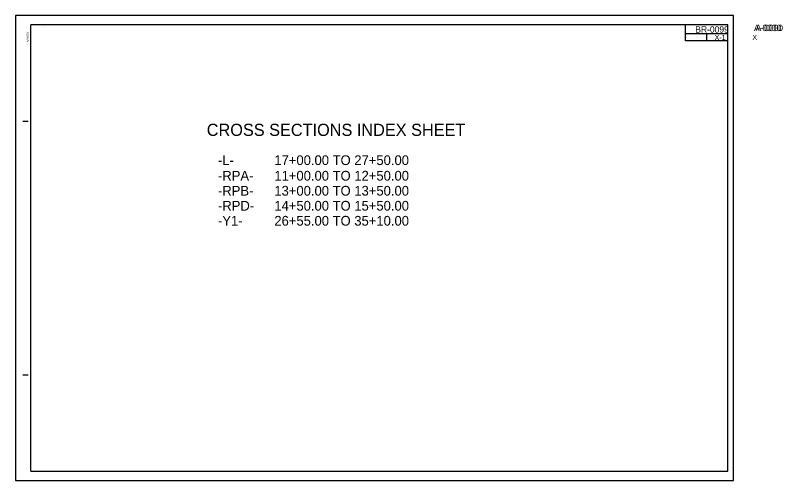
# Model space of a CAD drawing. Extents: x 1844463.5 to 1844493.8, y 671542 to 671578.6.
# Drawn here: x 1844463.49 to 1844493.76, y 671542.02 to 671560.35 of the extents above; entities that cross this region are included whole.
import ezdxf

# ---------------------------------------------------------------- set-up
doc = ezdxf.new("R2010")
doc.units = 0
for name, color, linetype in [('Sheet_Data_Text_CELL', 7, 'Continuous'), ('Sheet_Plan_CELL', 7, 'Continuous'), ('Sheet_Title_Block_Text', 7, 'Continuous'), ('z - Construction', 7, 'Continuous')]:
    doc.layers.add(name, color=color, linetype=linetype)

msp = doc.modelspace()

# ---------------------------------------------------------------- linework, layer by layer
at = {"layer": 'Sheet_Plan_CELL'}
for p, q in [((1844464.101, 671542.392), (1844464.101, 671559.975)), ((1844491.601, 671559.975), (1844464.101, 671559.975)), ((1844464.101, 671542.392), (1844464.101, 671559.975)), ((1844491.601, 671559.975), (1844464.101, 671559.975)), ((1844464.6, 671559.892), (1844464.6, 671559.892)), ((1844464.6, 671559.892), (1844464.6, 671559.892)), ((1844489.934, 671559.343), (1844489.934, 671559.975)), ((1844489.934, 671559.343), (1844489.934, 671559.975)), ((1844491.601, 671542.392), (1844491.601, 671559.975)), ((1844491.601, 671542.392), (1844491.601, 671559.975)), ((1844491.601, 671559.618), (1844489.934, 671559.618)), ((1844491.601, 671559.618), (1844489.934, 671559.618)), ((1844490.768, 671559.343), (1844490.768, 671559.618)), ((1844490.768, 671559.343), (1844490.768, 671559.618)), ((1844491.601, 671559.343), (1844489.934, 671559.343)), ((1844491.601, 671559.343), (1844489.934, 671559.343)), ((1844463.793, 671556.184), (1844464.002, 671556.184)), ((1844463.793, 671556.184), (1844464.002, 671556.184)), ((1844463.793, 671546.184), (1844464.002, 671546.184)), ((1844463.793, 671546.184), (1844464.002, 671546.184)), ((1844464.101, 671542.392), (1844491.601, 671542.392)), ((1844464.101, 671542.392), (1844491.601, 671542.392)), ((1844464.6, 671542.392), (1844464.6, 671542.392)), ((1844464.6, 671542.392), (1844464.6, 671542.392))]:
    msp.add_line(p, q, dxfattribs=at)
for centre in [(1844490.768, 671559.797), (1844490.768, 671559.797), (1844490.351, 671559.481), (1844490.351, 671559.481), (1844491.184, 671559.481), (1844491.184, 671559.481), (1844489.934, 671559.343), (1844489.934, 671559.343)]:
    msp.add_circle(centre, 0.001, dxfattribs=at)
at = {"layer": 'z - Construction'}
for p, q in [((1844491.826, 671560.35), (1844463.493, 671560.35)), ((1844463.493, 671560.35), (1844463.493, 671542.017)), ((1844491.826, 671560.35), (1844463.493, 671560.35)), ((1844463.493, 671560.35), (1844463.493, 671542.017)), ((1844491.826, 671542.017), (1844491.826, 671560.35)), ((1844491.826, 671542.017), (1844491.826, 671560.35)), ((1844463.493, 671542.017), (1844491.826, 671542.017)), ((1844463.493, 671542.017), (1844491.826, 671542.017))]:
    msp.add_line(p, q, dxfattribs=at)

# ---------------------------------------------------------------- texts
at = {"layer": 'Sheet_Data_Text_CELL'}
for s, height, p in [('CROSS SECTIONS INDEX SHEET', 0.48, (1844471.044, 671555.599)), ('-L-', 0.384, (1844471.487, 671554.452)), ('17+00.00 TO 27+50.00', 0.384, (1844473.71, 671554.452)), ('-RPA-', 0.384, (1844471.487, 671553.839)), ('11+00.00 TO 12+50.00', 0.384, (1844473.71, 671553.839)), ('-RPB-', 0.384, (1844471.487, 671553.247)), ('13+00.00 TO 13+50.00', 0.384, (1844473.71, 671553.247)), ('-RPD-', 0.384, (1844471.487, 671552.656)), ('14+50.00 TO 15+50.00', 0.384, (1844473.71, 671552.656)), ('-Y1-', 0.384, (1844471.487, 671552.064)), ('26+55.00 TO 35+10.00', 0.384, (1844473.71, 671552.064))]:
    msp.add_text(s, height=height, dxfattribs=at).set_placement(p)
at = {"layer": 'Sheet_Plan_CELL'}
msp.add_text('5/26/20', height=0.0875, rotation=90, dxfattribs=at).set_placement((1844464.023, 671559.296))
msp.add_text('5/26/20', height=0.0875, rotation=90, dxfattribs=at).set_placement((1844464.023, 671559.296))
at = {"layer": 'Sheet_Title_Block_Text'}
for s, height, p in [('BR-0099', 0.25, (1844490.317, 671559.671)), ('A-0000', 0.25, (1844492.63, 671559.73)), ('A-0000', 0.25, (1844492.696, 671559.73)), ('X-1', 0.2, (1844491.079, 671559.381)), ('X', 0.2, (1844492.566, 671559.381)), ('X', 0.2, (1844492.566, 671559.381))]:
    msp.add_text(s, height=height, dxfattribs=at).set_placement(p)

doc.saveas('drawing.dxf')
